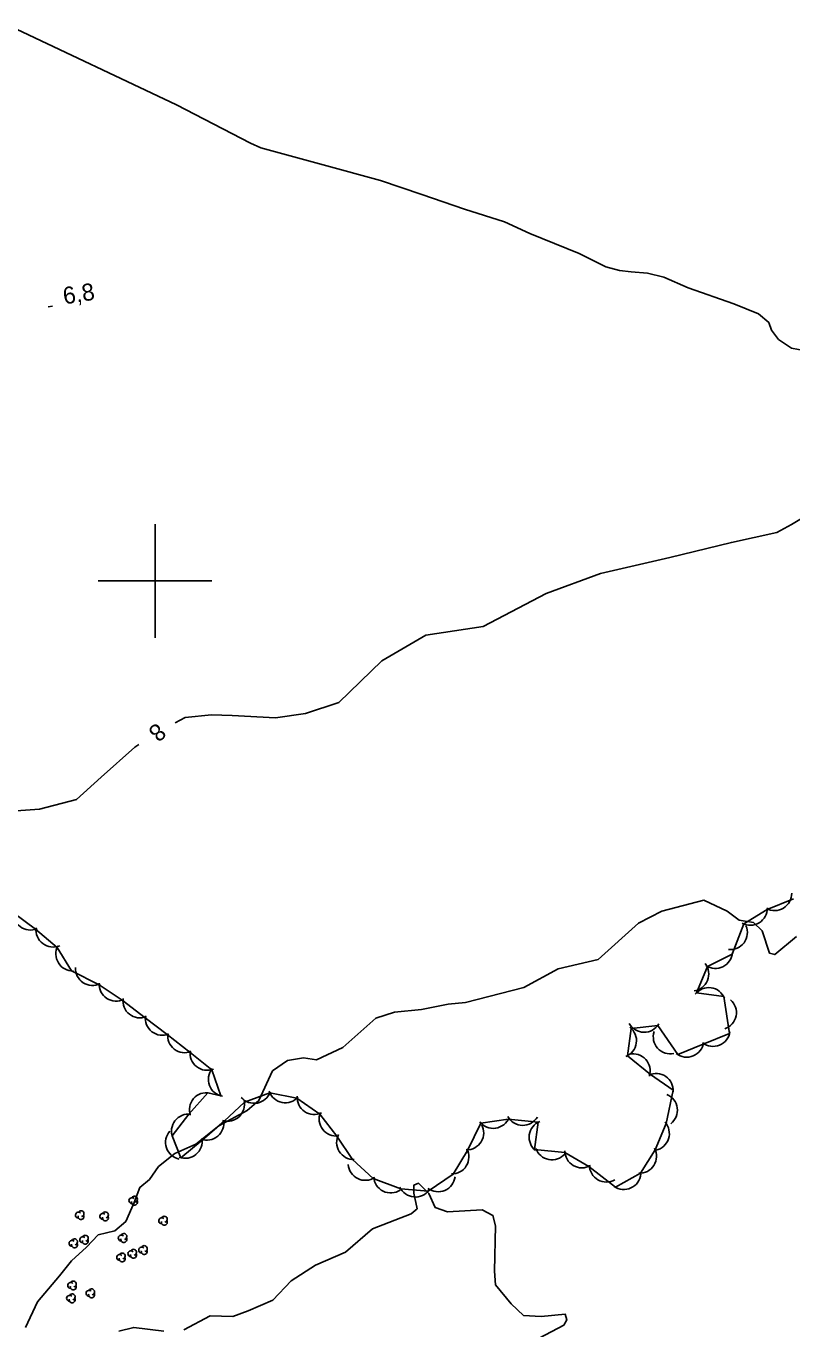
# Model space of a CAD drawing. Extents: x 643342 to 646936, y 5873857 to 5876103.
# Drawn here: x 645577.3 to 645712.2, y 5874668.3 to 5874897.7 of the extents above; entities that cross this region are included whole.
import ezdxf

# ---------------------------------------------------------------- set-up
doc = ezdxf.new("R2010")
doc.units = 0
for name, color, linetype in [('Niveau 1', 7, 'Continuous'), ('Niveau 2', 7, 'Continuous'), ('Niveau 22', 7, 'Continuous'), ('Niveau 3', 7, 'Continuous'), ('Niveau 44', 7, 'Continuous'), ('Niveau 61', 7, 'Continuous')]:
    doc.layers.add(name, color=color, linetype=linetype)

msp = doc.modelspace()

# ---------------------------------------------------------------- linework, layer by layer
at = {"layer": 'Niveau 1'}
for points in [[(645596.33, 5874690.53), (645597.3, 5874693.18), (645599.02, 5874694.59), (645600.61, 5874696.87), (645603.48, 5874699.18), (645607.18, 5874700.79), (645611.22, 5874704.01), (645616.24, 5874706.71), (645618.28, 5874708.49), (645620.7, 5874713.7), (645623.32, 5874715.52), (645626.16, 5874716.02), (645628.41, 5874715.65), (645633.06, 5874717.86), (645638.89, 5874723.01), (645642.15, 5874724.06), (645646.92, 5874724.52), (645651.6, 5874725.44), (645654.68, 5874725.77), (645664.92, 5874728.38), (645671, 5874731.67), (645678.03, 5874733.34), (645685.16, 5874739.7), (645689.22, 5874741.86), (645696.63, 5874743.79), (645700.76, 5874741.86), (645702.87, 5874740.26), (645705.36, 5874739.85), (645706.93, 5874738.38), (645708.23, 5874734.44), (645709.12, 5874734.21), (645712.98, 5874737.41)], [(645596.33, 5874690.53), (645594.87, 5874687.21), (645592.94, 5874685.54), (645590.01, 5874684.81), (645587.94, 5874682.67), (645585.3, 5874680.25), (645583.2, 5874677.64), (645579.32, 5874673.03), (645577.19, 5874668.54)]]:
    msp.add_lwpolyline(points, dxfattribs=at)
at = {"layer": 'Niveau 2'}
for points in [[(645720.02, 5874814.71), (645712.05, 5874809.93), (645709.52, 5874808.52), (645701.5, 5874806.79), (645690.68, 5874804.15), (645678.46, 5874801.3), (645668.86, 5874797.82), (645657.8, 5874792), (645647.7, 5874790.47), (645639.94, 5874785.94), (645632.39, 5874778.61), (645626.49, 5874776.67), (645621.2, 5874775.88), (645613.59, 5874776.28), (645609.94, 5874776.44), (645605.28, 5874775.93), (645603.54, 5874774.99)], [(645597.16, 5874771.2), (645596.44, 5874770.74), (645590.49, 5874765.45), (645586.15, 5874761.51), (645579.63, 5874759.82), (645573.08, 5874759.35)], [(645605.08, 5874668.12), (645609.7, 5874670.55), (645613.69, 5874670.43), (645616.43, 5874671.44), (645620.74, 5874673.33), (645624, 5874676.72), (645628.24, 5874679.48), (645633.57, 5874681.79), (645638.3, 5874685.87), (645645.13, 5874688.52), (645646.18, 5874689.42), (645645.56, 5874692.18), (645645.57, 5874693.58), (645646.37, 5874693.93), (645648.2, 5874692.13), (645649.32, 5874689.64), (645651.49, 5874688.86), (645657.61, 5874689.24), (645659.49, 5874688.26), (645659.98, 5874686.43), (645659.76, 5874678.46), (645659.95, 5874676.02), (645662.71, 5874672.71), (645664.86, 5874670.65), (645667.97, 5874670.46), (645672.21, 5874670.88), (645672.52, 5874669.85), (645672.01, 5874668.94), (645667.67, 5874666.64)], [(645593.61, 5874667.88), (645596.25, 5874668.54), (645601.58, 5874667.87)]]:
    msp.add_lwpolyline(points, dxfattribs=at)
at = {"layer": 'Niveau 22'}
msp.add_lwpolyline([(645714.53, 5874840.55), (645712.05, 5874841), (645709.77, 5874842.54), (645708.57, 5874844.2), (645708.06, 5874845.52), (645706.27, 5874847.03), (645701.92, 5874848.8), (645693.87, 5874851.62), (645689.61, 5874853.49), (645686.71, 5874854.22), (645683.86, 5874854.46), (645681.79, 5874854.67), (645679.39, 5874855.34), (645674.7, 5874857.67), (645666, 5874861.21), (645661.53, 5874863.27), (645654.5, 5874865.49), (645646.96, 5874868.06), (645639.71, 5874870.56), (645629.61, 5874873.3), (645618.62, 5874876.26), (645616.79, 5874877.08), (645603.81, 5874883.86), (645574.47, 5874897.74)], dxfattribs=at)
at = {"layer": 'Niveau 3'}
msp.add_line((645581.17, 5874848.29), (645581.96, 5874848.41), dxfattribs=at)
at = {"layer": 'Niveau 44'}
for points in [[(645602.12, 5874720.1), (645606.17, 5874716.93), (645609.98, 5874713.92), (645611.59, 5874709.31), (645609.31, 5874709.86), (645605.97, 5874706.11), (645603.03, 5874702.25), (645604.56, 5874698.4), (645608.29, 5874701.51), (645612.2, 5874704.88), (645615.73, 5874708.21), (645620.22, 5874709.84), (645624.98, 5874708.89), (645629.02, 5874706.08), (645631.99, 5874702.24), (645634.76, 5874698.12), (645638.42, 5874694.78), (645643.26, 5874692.96), (645648.1, 5874692.51), (645652.49, 5874695.55), (645655.03, 5874699.69), (645657.4, 5874704.5), (645662.2, 5874705.18), (645667.48, 5874704.68), (645666.8, 5874699.87), (645672.18, 5874699.33), (645676.38, 5874696.9), (645681.09, 5874693.21), (645685.5, 5874695.68), (645688.08, 5874699.79), (645689.98, 5874704.45), (645691.24, 5874710.34), (645687.23, 5874713.09), (645683.19, 5874716.38), (645683.87, 5874721.19), (645688.52, 5874721.72), (645692.05, 5874716.58), (645696.54, 5874718.41), (645701.17, 5874720.3), (645700.15, 5874726.79), (645695.34, 5874727.46), (645697.29, 5874732.08), (645701.63, 5874734.26), (645703.67, 5874739.6), (645707.82, 5874742.11), (645712.41, 5874744.01)], [(645575.05, 5874741.57), (645578.93, 5874738.66), (645582.76, 5874735.44), (645585.31, 5874731.31), (645590.16, 5874728.86), (645594.21, 5874726.19), (645598.29, 5874723.08), (645602.12, 5874720.1)]]:
    msp.add_lwpolyline(points, dxfattribs=at)
for centre, radius, start, end in [((645709.11, 5874744.95), 3, 241.1829, 1.1608), ((645709.11, 5874744.95), 3, 241.1829, 1.1608), ((645709.11, 5874744.95), 3, 241.1829, 1.1608), ((645578.04, 5874741.52), 3, 173.138, 293.1159), ((645578.04, 5874741.52), 3, 173.138, 293.1159), ((645578.04, 5874741.52), 3, 173.138, 293.1159), ((645704.83, 5874742.36), 3, 241.1829, 1.1608), ((645704.83, 5874742.36), 3, 241.1829, 1.1608), ((645704.83, 5874742.36), 3, 241.1829, 1.1608), ((645701.31, 5874738.08), 3, 263.4326, 23.4106), ((645701.31, 5874738.08), 3, 263.4326, 23.4106), ((645701.31, 5874738.08), 3, 263.4326, 23.4106), ((645582.04, 5874738.52), 3, 173.138, 293.1159), ((645582.04, 5874738.52), 3, 173.138, 293.1159), ((645582.04, 5874738.52), 3, 173.138, 293.1159), ((645585.54, 5874734.3), 3, 151.6052, 271.5831), ((645585.54, 5874734.3), 3, 151.6052, 271.5831), ((645585.54, 5874734.3), 3, 151.6052, 271.5831), ((645698.67, 5874734.75), 3, 236.5975, 356.5755), ((645698.67, 5874734.75), 3, 236.5975, 356.5755), ((645698.67, 5874734.75), 3, 236.5975, 356.5755), ((645694.51, 5874730.78), 3, 277.6904, 37.6684), ((645694.51, 5874730.78), 3, 277.6904, 37.6684), ((645694.51, 5874730.78), 3, 277.6904, 37.6684), ((645588.99, 5874731.75), 3, 176.5882, 296.5661), ((645588.99, 5874731.75), 3, 176.5882, 296.5661), ((645588.99, 5874731.75), 3, 176.5882, 296.5661), ((645593.16, 5874728.99), 3, 176.5882, 296.5661), ((645593.16, 5874728.99), 3, 176.5882, 296.5661), ((645593.16, 5874728.99), 3, 176.5882, 296.5661), ((645697.5, 5874725.38), 3, 22.0178, 141.9957), ((645697.5, 5874725.38), 3, 22.0178, 141.9957), ((645697.5, 5874725.38), 3, 22.0178, 141.9957), ((645597.34, 5874726.05), 3, 172.1403, 292.1182), ((645597.34, 5874726.05), 3, 172.1403, 292.1182), ((645597.34, 5874726.05), 3, 172.1403, 292.1182), ((645699.37, 5874723.98), 3, 288.5878, 48.5657), ((645699.37, 5874723.98), 3, 288.5878, 48.5657), ((645699.37, 5874723.98), 3, 288.5878, 48.5657), ((645601.29, 5874722.98), 3, 172.1403, 292.1182), ((645601.29, 5874722.98), 3, 172.1403, 292.1182), ((645601.29, 5874722.98), 3, 172.1403, 292.1182), ((645681.78, 5874719.03), 3, 291.9612, 51.9391), ((645681.78, 5874719.03), 3, 291.9612, 51.9391), ((645681.78, 5874719.03), 3, 291.9612, 51.9391), ((645686.12, 5874723.51), 3, 209.3355, 329.3135), ((645686.12, 5874723.51), 3, 209.3355, 329.3135), ((645686.12, 5874723.51), 3, 209.3355, 329.3135), ((645605.23, 5874719.91), 3, 172.1403, 292.1182), ((645605.23, 5874719.91), 3, 172.1403, 292.1182), ((645605.23, 5874719.91), 3, 172.1403, 292.1182), ((645690.74, 5874719.7), 3, 161.9165, 281.8944), ((645690.74, 5874719.7), 3, 161.9165, 281.8944), ((645690.74, 5874719.7), 3, 161.9165, 281.8944), ((645693.63, 5874719.13), 3, 232.2525, 352.2305), ((645693.63, 5874719.13), 3, 232.2525, 352.2305), ((645693.63, 5874719.13), 3, 232.2525, 352.2305), ((645698.26, 5874721.02), 3, 232.2525, 352.2305), ((645698.26, 5874721.02), 3, 232.2525, 352.2305), ((645698.26, 5874721.02), 3, 232.2525, 352.2305), ((645609.17, 5874716.81), 3, 171.5971, 291.5751), ((645609.17, 5874716.81), 3, 171.5971, 291.5751), ((645609.17, 5874716.81), 3, 171.5971, 291.5751), ((645684.2, 5874713.71), 3, 342.5547, 102.5327), ((645684.2, 5874713.71), 3, 342.5547, 102.5327), ((645684.2, 5874713.71), 3, 342.5547, 102.5327), ((645612.39, 5874712.2), 3, 140.579, 260.557), ((645612.39, 5874712.2), 3, 140.579, 260.557), ((645612.39, 5874712.2), 3, 140.579, 260.557), ((645688.24, 5874710.26), 3, 355.5563, 115.5342), ((645688.24, 5874710.26), 3, 355.5563, 115.5342), ((645688.24, 5874710.26), 3, 355.5563, 115.5342), ((645609.05, 5874706.87), 3, 79.1489, 199.1268), ((645609.05, 5874706.87), 3, 79.1489, 199.1268), ((645609.05, 5874706.87), 3, 79.1489, 199.1268), ((645617.47, 5874711), 3, 220.6083, 340.5862), ((645617.47, 5874711), 3, 220.6083, 340.5862), ((645617.47, 5874711), 3, 220.6083, 340.5862), ((645622.95, 5874711.09), 3, 198.7592, 318.7371), ((645622.95, 5874711.09), 3, 198.7592, 318.7371), ((645622.95, 5874711.09), 3, 198.7592, 318.7371), ((645628.04, 5874709.02), 3, 175.5669, 295.5448), ((645628.04, 5874709.02), 3, 175.5669, 295.5448), ((645628.04, 5874709.02), 3, 175.5669, 295.5448), ((645688.98, 5874706.79), 3, 307.5988, 67.5767), ((645688.98, 5874706.79), 3, 307.5988, 67.5767), ((645688.98, 5874706.79), 3, 307.5988, 67.5767), ((645612.75, 5874707.83), 3, 253.3578, 13.3358), ((645612.75, 5874707.83), 3, 253.3578, 13.3358), ((645612.75, 5874707.83), 3, 253.3578, 13.3358), ((645605.9, 5874703.11), 3, 82.6307, 202.6086), ((645605.9, 5874703.11), 3, 82.6307, 202.6086), ((645605.9, 5874703.11), 3, 82.6307, 202.6086), ((645609.13, 5874704.51), 3, 249.9262, 9.9042), ((645609.13, 5874704.51), 3, 249.9262, 9.9042), ((645609.13, 5874704.51), 3, 249.9262, 9.9042), ((645631.9, 5874705.24), 3, 157.7152, 277.6931), ((645631.9, 5874705.24), 3, 157.7152, 277.6931), ((645631.9, 5874705.24), 3, 157.7152, 277.6931), ((645659.55, 5874706.59), 3, 218.0869, 338.0648), ((645659.55, 5874706.59), 3, 218.0869, 338.0648), ((645659.55, 5874706.59), 3, 218.0869, 338.0648), ((645664.75, 5874707.12), 3, 209.1383, 329.1162), ((645664.75, 5874707.12), 3, 209.1383, 329.1162), ((645664.75, 5874707.12), 3, 209.1383, 329.1162), ((645668.88, 5874702.02), 3, 111.8752, 231.8532), ((645668.88, 5874702.02), 3, 111.8752, 231.8532), ((645668.88, 5874702.02), 3, 111.8752, 231.8532), ((645687.57, 5874702.67), 3, 282.2639, 42.2418), ((645687.57, 5874702.67), 3, 282.2639, 42.2418), ((645687.57, 5874702.67), 3, 282.2639, 42.2418), ((645604.86, 5874701.11), 3, 138.3547, 258.3327), ((645604.86, 5874701.11), 3, 138.3547, 258.3327), ((645604.86, 5874701.11), 3, 138.3547, 258.3327), ((645634.98, 5874701.11), 3, 151.9011, 271.8791), ((645634.98, 5874701.11), 3, 151.9011, 271.8791), ((645634.98, 5874701.11), 3, 151.9011, 271.8791), ((645654.88, 5874702.8), 3, 268.4321, 28.4101), ((645654.88, 5874702.8), 3, 268.4321, 28.4101), ((645654.88, 5874702.8), 3, 268.4321, 28.4101), ((645605.29, 5874701.31), 3, 249.9262, 9.9042), ((645605.29, 5874701.31), 3, 249.9262, 9.9042), ((645605.29, 5874701.31), 3, 249.9262, 9.9042), ((645669.9, 5874701.04), 3, 198.881, 318.8589), ((645669.9, 5874701.04), 3, 198.881, 318.8589), ((645669.9, 5874701.04), 3, 198.881, 318.8589), ((645685.3, 5874698.67), 3, 267.9149, 27.8928), ((645685.3, 5874698.67), 3, 267.9149, 27.8928), ((645685.3, 5874698.67), 3, 267.9149, 27.8928), ((645652.26, 5874698.55), 3, 268.4321, 28.4101), ((645652.26, 5874698.55), 3, 268.4321, 28.4101), ((645652.26, 5874698.55), 3, 268.4321, 28.4101), ((645675.16, 5874699.64), 3, 179.9549, 299.9329), ((645675.16, 5874699.64), 3, 179.9549, 299.9329), ((645675.16, 5874699.64), 3, 179.9549, 299.9329), ((645637.02, 5874697.43), 3, 183.7844, 303.7624), ((645637.02, 5874697.43), 3, 183.7844, 303.7624), ((645637.02, 5874697.43), 3, 183.7844, 303.7624), ((645679.49, 5874697.13), 3, 179.9549, 299.9329), ((645679.49, 5874697.13), 3, 179.9549, 299.9329), ((645679.49, 5874697.13), 3, 179.9549, 299.9329), ((645682.56, 5874695.82), 3, 234.6696, 354.6475), ((645682.56, 5874695.82), 3, 234.6696, 354.6475), ((645682.56, 5874695.82), 3, 234.6696, 354.6475), ((645641.51, 5874695.22), 3, 183.7844, 303.7624), ((645641.51, 5874695.22), 3, 183.7844, 303.7624), ((645641.51, 5874695.22), 3, 183.7844, 303.7624), ((645645.85, 5874694.49), 3, 204.6626, 324.6405), ((645645.85, 5874694.49), 3, 204.6626, 324.6405), ((645645.85, 5874694.49), 3, 204.6626, 324.6405), ((645649.86, 5874695.42), 3, 233.0283, 353.0062), ((645649.86, 5874695.42), 3, 233.0283, 353.0062), ((645649.86, 5874695.42), 3, 233.0283, 353.0062), ((645595.93, 5874690.86), 0.523, 44.1154, 269.804), ((645596.38, 5874690.6), 0.523, 166.9369, 29.6212), ((645596.38, 5874691.12), 0.523, 282.2692, 149.7263), ((645586.51, 5874688.3), 0.523, 44.1154, 269.804), ((645586.96, 5874688.56), 0.523, 282.2692, 149.7263), ((645590.81, 5874688.09), 0.523, 44.1154, 269.804), ((645591.26, 5874688.35), 0.523, 282.2692, 149.7263), ((645586.96, 5874688.04), 0.523, 166.9369, 29.6212), ((645591.26, 5874687.83), 0.523, 166.9369, 29.6212), ((645601.19, 5874687.32), 0.523, 44.1154, 269.804), ((645601.64, 5874687.06), 0.523, 166.9369, 29.6212), ((645601.64, 5874687.58), 0.523, 282.2692, 149.7263), ((645585.83, 5874683.6), 0.523, 282.2692, 149.7263), ((645587.27, 5874683.98), 0.523, 44.1154, 269.804), ((645587.72, 5874683.72), 0.523, 166.9369, 29.6212), ((645587.72, 5874684.24), 0.523, 282.2692, 149.7263), ((645594.06, 5874684.28), 0.523, 44.1154, 269.804), ((645594.51, 5874684.02), 0.523, 166.9369, 29.6212), ((645594.51, 5874684.54), 0.523, 282.2692, 149.7263), ((645585.38, 5874683.34), 0.523, 44.1154, 269.804), ((645585.83, 5874683.08), 0.523, 166.9369, 29.6212), ((645594.22, 5874681.1), 0.523, 282.2692, 149.7263), ((645595.76, 5874681.5), 0.523, 44.1154, 269.804), ((645596.21, 5874681.76), 0.523, 282.2692, 149.7263), ((645597.65, 5874682.15), 0.523, 44.1154, 269.804), ((645598.1, 5874681.89), 0.523, 166.9369, 29.6212), ((645598.1, 5874682.41), 0.523, 282.2692, 149.7263), ((645593.77, 5874680.84), 0.523, 44.1154, 269.804), ((645594.22, 5874680.58), 0.523, 166.9369, 29.6212), ((645596.21, 5874681.24), 0.523, 166.9369, 29.6212), ((645585.15, 5874675.91), 0.523, 44.1154, 269.804), ((645585.6, 5874675.65), 0.523, 166.9369, 29.6212), ((645585.6, 5874676.17), 0.523, 282.2692, 149.7263), ((645588.38, 5874674.54), 0.523, 44.1154, 269.804), ((645588.83, 5874674.8), 0.523, 282.2692, 149.7263), ((645584.96, 5874673.66), 0.523, 44.1154, 269.804), ((645585.41, 5874673.4), 0.523, 166.9369, 29.6212), ((645585.41, 5874673.92), 0.523, 282.2692, 149.7263), ((645588.83, 5874674.28), 0.523, 166.9369, 29.6212)]:
    msp.add_arc(centre, radius, start, end, dxfattribs=at)
at = {"layer": 'Niveau 61'}
for points in [[(645600, 5874810), (645600, 5874800), (645600, 5874790)], [(645590, 5874800), (645600, 5874800), (645610, 5874800)]]:
    msp.add_lwpolyline(points, dxfattribs=at)

# ---------------------------------------------------------------- texts
at = {"layer": 'Niveau 2'}
msp.add_text('8', height=3, rotation=221.4942, dxfattribs=at).set_placement((645600.27, 5874775.17))
at = {"layer": 'Niveau 3'}
msp.add_text('6,8  ', height=3, rotation=8.9405, dxfattribs=at).set_placement((645584.03, 5874848.7))

doc.saveas('drawing.dxf')
